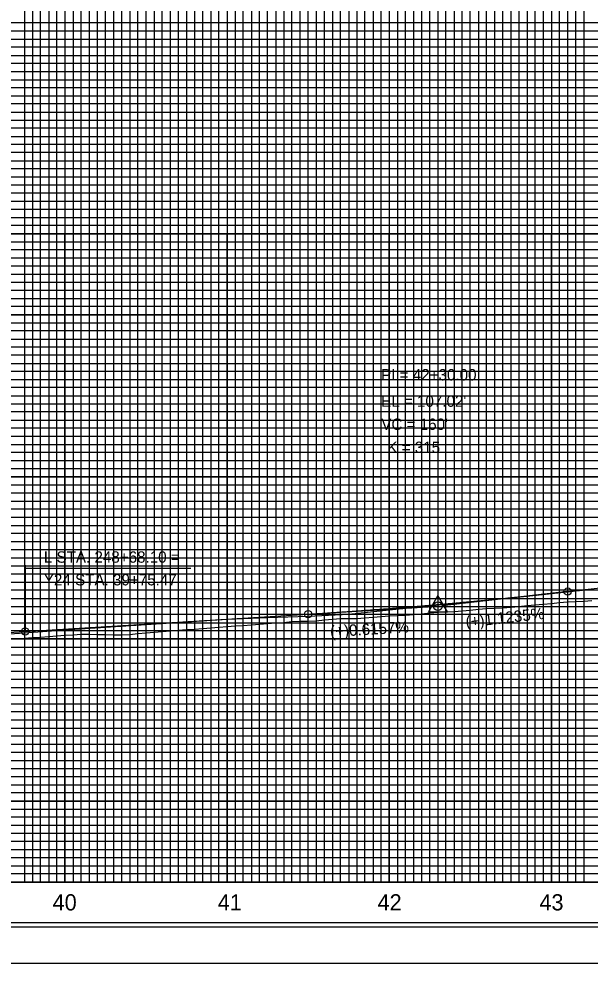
# Model space of a CAD drawing. Extents: x 2345490 to 2436403, y 465165 to 573888.
# Drawn here: x 2384738 to 2385091, y 515088 to 515670 of the extents above; entities that cross this region are included whole.
import ezdxf

# ---------------------------------------------------------------- set-up
doc = ezdxf.new("R2010")
doc.units = 0
for name, color, linetype in [('Old_Level_1', 7, 'Continuous'), ('Old_Level_18', 7, 'Continuous'), ('Old_Level_2', 7, 'Continuous'), ('Old_Level_3', 7, 'Continuous'), ('Old_Level_41', 7, 'Continuous'), ('Old_Level_42', 7, 'Continuous'), ('Old_Level_43', 7, 'Continuous'), ('Old_Level_50', 7, 'Continuous'), ('Old_Level_51', 7, 'Continuous'), ('Old_Level_57', 7, 'Continuous'), ('Old_Level_61', 7, 'Continuous'), ('Old_Level_62', 7, 'Continuous'), ('Old_Level_63', 7, 'Continuous')]:
    doc.layers.add(name, color=color, linetype=linetype)

msp = doc.modelspace()

# ---------------------------------------------------------------- linework, layer by layer
at = {"layer": 'Old_Level_1'}
for points in [[(2384766.799, 515289.75575), (2384771.799, 515290.10525), (2384776.799, 515290.37575), (2384781.799, 515290.40025), (2384786.799, 515290.303), (2384791.799, 515290.20375), (2384796.799, 515290.1025), (2384801.799, 515289.9995), (2384806.799, 515290.20875), (2384811.799, 515290.93725), (2384816.799, 515291.29), (2384821.799, 515291.61975), (2384826.799, 515292.0715), (2384831.799, 515292.55775), (2384836.799, 515292.92775), (2384841.799, 515293.286), (2384846.799, 515293.642), (2384851.799, 515294.027), (2384856.799, 515294.433), (2384861.799, 515294.83025), (2384866.799, 515295.1785), (2384871.799, 515295.52475), (2384876.799, 515295.869), (2384881.799, 515296.26675), (2384886.799, 515296.664), (2384891.799, 515297.05825), (2384896.799, 515297.394), (2384901.799, 515297.728), (2384906.799, 515298.30625), (2384911.799, 515298.3895), (2384916.799, 515298.471), (2384921.799, 515298.69675), (2384926.799, 515299.20875), (2384931.799, 515299.719), (2384936.799, 515300.07525), (2384941.799, 515300.148), (2384946.799, 515300.2205), (2384951.799, 515300.44075), (2384956.799, 515300.94775), (2384961.799, 515301.45475), (2384966.799, 515301.793), (2384971.799, 515302.0295), (2384976.799, 515302.266), (2384981.799, 515302.5435), (2384986.799, 515303.05425), (2384991.799, 515303.565), (2384996.799, 515304.03225), (2385001.799, 515304.2685), (2385006.799, 515304.50475), (2385011.799, 515304.782), (2385016.799, 515305.293), (2385021.799, 515305.804), (2385026.799, 515306.27125), (2385031.799, 515306.50725), (2385036.799, 515306.74325), (2385041.799, 515307.02025), (2385046.799, 515307.5315), (2385051.799, 515308.04275), (2385056.799, 515308.519), (2385061.799, 515308.86675), (2385066.799, 515309.378), (2385071.799, 515309.88925), (2385076.799, 515310.32875), (2385081.799, 515310.621), (2385086.799, 515310.91325), (2385091.799, 515311.27425)], [(2384736.799, 515287.50825), (2384741.799, 515287.97125), (2384746.799, 515288.333), (2384751.799, 515288.69225), (2384756.799, 515289.04925), (2384761.799, 515289.40375), (2384766.799, 515289.75575)]]:
    msp.add_lwpolyline(points, dxfattribs=at)
at = {"layer": 'Old_Level_18'}
msp.add_lwpolyline([(2386016.79875, 516162.5265), (2384516.79875, 516162.5265), (2384516.79875, 515112.5265), (2386016.79875, 515112.5265)], close=True, dxfattribs=at)
at = {"layer": 'Old_Level_2'}
for p, q in [((2384742.26875, 515292.0555), (2384742.26875, 515331.041)), ((2385076.799, 515316.71475), (2384999.532, 515308.034)), ((2385076.799, 515316.71475), (2385096.799, 515318.962)), ((2384626.799, 515284.94625), (2384916.799, 515302.80125)), ((2384916.799, 515302.80125), (2384994.05425, 515307.558))]:
    msp.add_line(p, q, dxfattribs=at)
msp.add_lwpolyline([(2384990.99325, 515304.27575), (2385002.73575, 515304.27575), (2384996.86475, 515314.4015)], close=True, dxfattribs=at)
for centre, radius in [((2385076.799, 515316.71475), 2.25), ((2384996.799, 515307.72675), 2.75), ((2384996.799, 515307.72675), 2.75), ((2384916.799, 515302.80125), 2.25), ((2384742.26875, 515292.0555), 2.25)]:
    msp.add_circle(centre, radius, dxfattribs=at)
msp.add_spline([(2384916.799, 515302.80125), (2384919.999, 515302.99975), (2384923.199, 515303.20175), (2384926.399, 515303.40675), (2384929.599, 515303.61525), (2384932.799, 515303.82675), (2384935.999, 515304.04175), (2384939.199, 515304.26), (2384942.399, 515304.48125), (2384945.599, 515304.706), (2384948.799, 515304.93375), (2384951.999, 515305.165), (2384955.199, 515305.3995), (2384958.399, 515305.637), (2384961.599, 515305.878), (2384964.799, 515306.122), (2384967.999, 515306.3695), (2384971.199, 515306.62), (2384974.399, 515306.874), (2384977.599, 515307.13125), (2384980.799, 515307.3915), (2384983.999, 515307.65525), (2384987.199, 515307.922), (2384990.399, 515308.19225), (2384993.599, 515308.46575), (2384996.799, 515308.74225), (2384999.999, 515309.02225), (2385003.199, 515309.30525), (2385006.399, 515309.59175), (2385009.599, 515309.8815), (2385012.799, 515310.17425), (2385015.999, 515310.4705), (2385019.199, 515310.76975), (2385022.399, 515311.0725), (2385025.599, 515311.3785), (2385028.799, 515311.6875), (2385031.999, 515312), (2385035.199, 515312.3155), (2385038.399, 515312.6345), (2385041.599, 515312.95675), (2385044.799, 515313.282), (2385047.999, 515313.61075), (2385051.199, 515313.94275), (2385054.399, 515314.27775), (2385057.599, 515314.61625), (2385060.799, 515314.95775), (2385063.999, 515315.30275), (2385067.199, 515315.651), (2385070.399, 515316.00225), (2385073.599, 515316.357), (2385076.799, 515316.71475)], degree=3, dxfattribs=at)
at = {"layer": 'Old_Level_3'}
for p, q in [((2384742.26875, 515332.9975), (2384742.26875, 515292.0555)), ((2384844.445, 515331.041), (2384742.26875, 515331.041))]:
    msp.add_line(p, q, dxfattribs=at)
at = {"layer": 'Old_Level_41'}
msp.add_line((2386016.79875, 515137.5265), (2384516.79875, 515137.5265), dxfattribs=at)
for points in [[(2384516.79875, 516162.5265), (2384566.79875, 516162.5265), (2384566.79875, 515137.5265), (2384616.79875, 515137.5265), (2384616.79875, 516162.5265), (2384666.79875, 516162.5265), (2384666.79875, 515137.5265), (2384716.79875, 515137.5265), (2384716.79875, 516162.5265), (2384766.79875, 516162.5265), (2384766.79875, 515137.5265), (2384816.79875, 515137.5265), (2384816.79875, 516162.5265), (2384866.79875, 516162.5265), (2384866.79875, 515137.5265), (2384916.79875, 515137.5265), (2384916.79875, 516162.5265), (2384966.79875, 516162.5265), (2384966.79875, 515137.5265), (2385016.79875, 515137.5265), (2385016.79875, 516162.5265), (2385066.79875, 516162.5265), (2385066.79875, 515137.5265), (2385116.79875, 515137.5265)], [(2384591.79875, 515137.5265), (2384591.79875, 516162.5265), (2384641.79875, 516162.5265), (2384641.79875, 515137.5265), (2384691.79875, 515137.5265), (2384691.79875, 516162.5265), (2384741.79875, 516162.5265), (2384741.79875, 515137.5265), (2384791.79875, 515137.5265), (2384791.79875, 516162.5265), (2384841.79875, 516162.5265), (2384841.79875, 515137.5265), (2384891.79875, 515137.5265), (2384891.79875, 516162.5265), (2384941.79875, 516162.5265), (2384941.79875, 515137.5265), (2384991.79875, 515137.5265), (2384991.79875, 516162.5265), (2385041.79875, 516162.5265), (2385041.79875, 515137.5265), (2385091.79875, 515137.5265)], [(2386016.79875, 515662.5265), (2384516.79875, 515662.5265), (2384516.79875, 515612.5265), (2386016.79875, 515612.5265)], [(2386016.79875, 515562.5265), (2384516.79875, 515562.5265), (2384516.79875, 515512.5265), (2386016.79875, 515512.5265)], [(2386016.79875, 515487.5265), (2384516.79875, 515487.5265), (2384516.79875, 515537.5265), (2386016.79875, 515537.5265)], [(2386016.79875, 515462.5265), (2384516.79875, 515462.5265), (2384516.79875, 515412.5265), (2386016.79875, 515412.5265)], [(2386016.79875, 515387.5265), (2384516.79875, 515387.5265), (2384516.79875, 515437.5265), (2386016.79875, 515437.5265)], [(2386016.79875, 515362.5265), (2384516.79875, 515362.5265), (2384516.79875, 515312.5265), (2386016.79875, 515312.5265)], [(2386016.79875, 515262.5265), (2384516.79875, 515262.5265), (2384516.79875, 515212.5265), (2386016.79875, 515212.5265)], [(2386016.79875, 515187.5265), (2384516.79875, 515187.5265), (2384516.79875, 515237.5265), (2386016.79875, 515237.5265)], [(2386016.79875, 515162.5265), (2384516.79875, 515162.5265)]]:
    msp.add_lwpolyline(points, dxfattribs=at)
at = {"layer": 'Old_Level_42'}
for points in [[(2386016.79875, 515587.5265), (2384516.79875, 515587.5265), (2384516.79875, 515637.5265), (2386016.79875, 515637.5265)], [(2386016.79875, 515287.5265), (2384516.79875, 515287.5265), (2384516.79875, 515337.5265), (2386016.79875, 515337.5265)]]:
    msp.add_lwpolyline(points, dxfattribs=at)
at = {"layer": 'Old_Level_43'}
for points in [[(2384746.79875, 516162.5265), (2384746.79875, 515137.5265), (2384751.79875, 515137.5265), (2384751.79875, 516162.5265)], [(2384756.79875, 516162.5265), (2384756.79875, 515137.5265), (2384761.79875, 515137.5265), (2384761.79875, 516162.5265)], [(2384771.79875, 516162.5265), (2384771.79875, 515137.5265), (2384776.79875, 515137.5265), (2384776.79875, 516162.5265)], [(2384781.79875, 516162.5265), (2384781.79875, 515137.5265), (2384786.79875, 515137.5265), (2384786.79875, 516162.5265)], [(2384796.79875, 516162.5265), (2384796.79875, 515137.5265), (2384801.79875, 515137.5265), (2384801.79875, 516162.5265)], [(2384806.79875, 516162.5265), (2384806.79875, 515137.5265), (2384811.79875, 515137.5265), (2384811.79875, 516162.5265)], [(2384821.79875, 516162.5265), (2384821.79875, 515137.5265), (2384826.79875, 515137.5265), (2384826.79875, 516162.5265)], [(2384831.79875, 516162.5265), (2384831.79875, 515137.5265), (2384836.79875, 515137.5265), (2384836.79875, 516162.5265)], [(2384846.79875, 516162.5265), (2384846.79875, 515137.5265), (2384851.79875, 515137.5265), (2384851.79875, 516162.5265)], [(2384856.79875, 516162.5265), (2384856.79875, 515137.5265), (2384861.79875, 515137.5265), (2384861.79875, 516162.5265)], [(2384871.79875, 516162.5265), (2384871.79875, 515137.5265), (2384876.79875, 515137.5265), (2384876.79875, 516162.5265)], [(2384881.79875, 516162.5265), (2384881.79875, 515137.5265), (2384886.79875, 515137.5265), (2384886.79875, 516162.5265)], [(2384896.79875, 516162.5265), (2384896.79875, 515137.5265), (2384911.79875, 515137.5265), (2384911.79875, 516162.5265)], [(2384901.79875, 516162.5265), (2384901.79875, 515137.5265), (2384906.79875, 515137.5265), (2384906.79875, 516162.5265)], [(2384901.79875, 516161.9265), (2384901.79875, 515137.5265), (2384906.79875, 515137.5265), (2384906.79875, 516161.9265)], [(2384921.79875, 516162.5265), (2384921.79875, 515137.5265), (2384926.79875, 515137.5265), (2384926.79875, 516162.5265)], [(2384931.79875, 516162.5265), (2384931.79875, 515137.5265), (2384936.79875, 515137.5265), (2384936.79875, 516162.5265)], [(2384946.79875, 516162.5265), (2384946.79875, 515137.5265), (2384951.79875, 515137.5265), (2384951.79875, 516162.5265)], [(2384956.79875, 516162.5265), (2384956.79875, 515137.5265), (2384961.79875, 515137.5265), (2384961.79875, 516162.5265)], [(2384971.79875, 516162.5265), (2384971.79875, 515137.5265), (2384976.79875, 515137.5265), (2384976.79875, 516162.5265)], [(2384981.79875, 516162.5265), (2384981.79875, 515137.5265), (2384986.79875, 515137.5265), (2384986.79875, 516162.5265)], [(2384996.79875, 516162.5265), (2384996.79875, 515137.5265), (2385001.79875, 515137.5265), (2385001.79875, 516162.5265)], [(2385006.79875, 516162.5265), (2385006.79875, 515137.5265), (2385011.79875, 515137.5265), (2385011.79875, 516162.5265)], [(2385021.79875, 516162.5265), (2385021.79875, 515137.5265), (2385026.79875, 515137.5265), (2385026.79875, 516162.5265)], [(2385031.79875, 516162.5265), (2385031.79875, 515137.5265), (2385036.79875, 515137.5265), (2385036.79875, 516162.5265)], [(2385046.79875, 516162.5265), (2385046.79875, 515137.5265)], [(2385051.79875, 516162.5265), (2385051.79875, 515137.5265), (2385056.79875, 515137.5265), (2385056.79875, 516162.5265), (2385061.79875, 516162.5265), (2385061.79875, 515137.5265), (2385071.79875, 515137.5265), (2385071.79875, 516162.5265), (2385076.79875, 516162.5265), (2385076.79875, 515137.5265), (2385081.79875, 515137.5265), (2385081.79875, 516162.5265), (2385086.79875, 516162.5265), (2385086.79875, 515137.5265)], [(2385966.79875, 515667.5265), (2384566.79875, 515667.5265), (2384566.79875, 515657.5265), (2385966.79875, 515657.5265)], [(2385966.79875, 515652.5265), (2384566.79875, 515652.5265), (2384566.79875, 515647.5265), (2385966.79875, 515647.5265)], [(2385966.79875, 515642.5265), (2384566.79875, 515642.5265)], [(2384566.79875, 515632.5265), (2385966.79875, 515632.5265)], [(2385966.79875, 515627.5265), (2384566.79875, 515627.5265), (2384566.79875, 515622.5265), (2385966.79875, 515622.5265)], [(2385966.79875, 515617.5265), (2384566.79875, 515617.5265), (2384566.79875, 515607.5265), (2385966.79875, 515607.5265)], [(2385966.79875, 515602.5265), (2384566.79875, 515602.5265), (2384566.79875, 515597.5265), (2385966.79875, 515597.5265)], [(2385966.79875, 515592.5265), (2384566.79875, 515592.5265), (2384566.79875, 515582.5265), (2385966.79875, 515582.5265)], [(2385966.79875, 515577.5265), (2384566.79875, 515577.5265), (2384566.79875, 515572.5265), (2385966.79875, 515572.5265)], [(2385966.79875, 515567.5265), (2384566.79875, 515567.5265), (2384566.79875, 515557.5265), (2385966.79875, 515557.5265)], [(2385966.79875, 515552.5265), (2384566.79875, 515552.5265), (2384566.79875, 515547.5265), (2385966.79875, 515547.5265)], [(2385966.79875, 515542.5265), (2384566.79875, 515542.5265), (2384566.79875, 515532.5265), (2385966.79875, 515532.5265)], [(2385966.79875, 515527.5265), (2384566.79875, 515527.5265), (2384566.79875, 515522.5265), (2385966.79875, 515522.5265)], [(2385966.79875, 515517.5265), (2384566.79875, 515517.5265), (2384566.79875, 515507.5265), (2385966.79875, 515507.5265)], [(2385966.79875, 515502.5265), (2384566.79875, 515502.5265), (2384566.79875, 515497.5265), (2385966.79875, 515497.5265)], [(2385966.79875, 515492.5265), (2384566.79875, 515492.5265), (2384566.79875, 515482.5265), (2385966.79875, 515482.5265)], [(2385966.79875, 515477.5265), (2384566.79875, 515477.5265), (2384566.79875, 515472.5265), (2385966.79875, 515472.5265)], [(2385966.79875, 515467.5265), (2384566.79875, 515467.5265), (2384566.79875, 515457.5265), (2385966.79875, 515457.5265)], [(2385966.79875, 515452.5265), (2384566.79875, 515452.5265), (2384566.79875, 515447.5265), (2385966.79875, 515447.5265)], [(2385966.79875, 515442.5265), (2384566.79875, 515442.5265), (2384566.79875, 515432.5265), (2385966.79875, 515432.5265)], [(2385966.79875, 515427.5265), (2384566.79875, 515427.5265), (2384566.79875, 515422.5265), (2385966.79875, 515422.5265)], [(2385966.79875, 515417.5265), (2384566.79875, 515417.5265), (2384566.79875, 515407.5265), (2385966.79875, 515407.5265)], [(2385966.79875, 515402.5265), (2384566.79875, 515402.5265), (2384566.79875, 515397.5265), (2385966.79875, 515397.5265)], [(2385966.79875, 515392.5265), (2384566.79875, 515392.5265), (2384566.79875, 515382.5265), (2385966.79875, 515382.5265)], [(2385966.79875, 515377.5265), (2384566.79875, 515377.5265), (2384566.79875, 515372.5265), (2385966.79875, 515372.5265)], [(2385966.79875, 515367.5265), (2384566.79875, 515367.5265), (2384566.79875, 515357.5265), (2385966.79875, 515357.5265)], [(2385966.79875, 515352.5265), (2384566.79875, 515352.5265), (2384566.79875, 515347.5265), (2385966.79875, 515347.5265)], [(2385966.79875, 515342.5265), (2384566.79875, 515342.5265)], [(2384566.79875, 515332.5265), (2385966.79875, 515332.5265)], [(2385966.79875, 515327.5265), (2384566.79875, 515327.5265), (2384566.79875, 515322.5265), (2385966.79875, 515322.5265)], [(2385966.79875, 515317.5265), (2384566.79875, 515317.5265)], [(2384566.79875, 515307.5265), (2385966.79875, 515307.5265)], [(2385966.79875, 515302.5265), (2384566.79875, 515302.5265), (2384566.79875, 515297.5265), (2385966.79875, 515297.5265)], [(2385966.79875, 515292.5265), (2384566.79875, 515292.5265), (2384566.79875, 515282.5265), (2385966.79875, 515282.5265)], [(2385966.79875, 515277.5265), (2384566.79875, 515277.5265), (2384566.79875, 515272.5265), (2385966.79875, 515272.5265)], [(2385966.79875, 515267.5265), (2384566.79875, 515267.5265), (2384566.79875, 515257.5265), (2385966.79875, 515257.5265)], [(2385966.79875, 515252.5265), (2384566.79875, 515252.5265), (2384566.79875, 515247.5265), (2385966.79875, 515247.5265)], [(2385966.79875, 515242.5265), (2384566.79875, 515242.5265), (2384566.79875, 515232.5265), (2385966.79875, 515232.5265)], [(2385966.79875, 515227.5265), (2384566.79875, 515227.5265), (2384566.79875, 515222.5265), (2385966.79875, 515222.5265)], [(2385966.79875, 515217.5265), (2384566.79875, 515217.5265), (2384566.79875, 515207.5265), (2385966.79875, 515207.5265)], [(2385966.79875, 515202.5265), (2384566.79875, 515202.5265), (2384566.79875, 515197.5265), (2385966.79875, 515197.5265)], [(2385966.79875, 515192.5265), (2384566.79875, 515192.5265), (2384566.79875, 515182.5265), (2385966.79875, 515182.5265)], [(2385966.79875, 515177.5265), (2384566.79875, 515177.5265), (2384566.79875, 515172.5265), (2385966.79875, 515172.5265)], [(2385966.79875, 515167.5265), (2384566.79875, 515167.5265), (2384566.79875, 515157.5265), (2385966.79875, 515157.5265)], [(2385966.79875, 515152.5265), (2384566.79875, 515152.5265), (2384566.79875, 515147.5265), (2385966.79875, 515147.5265)], [(2385966.79875, 515142.5265), (2384566.79875, 515142.5265)]]:
    msp.add_lwpolyline(points, dxfattribs=at)
at = {"layer": 'Old_Level_50'}
msp.add_lwpolyline([(2386029.29875, 516165.0765), (2384362.79875, 516165.0765), (2384362.79875, 515109.9765), (2386029.29875, 515109.9765)], close=True, dxfattribs=at)
at = {"layer": 'Old_Level_51'}
msp.add_lwpolyline([(2386033.79875, 516187.5265), (2384349.79875, 516187.5265), (2384349.79875, 515087.5265), (2386033.79875, 515087.5265)], close=True, dxfattribs=at)
at = {"layer": 'Old_Level_57'}
for p, q in [((2381716.79925, 515537.52675), (2386366.79875, 515537.52675)), ((2384766.79875, 515137.52675), (2384766.79875, 515537.52675)), ((2384766.79875, 515137.62675), (2384766.79875, 515537.52675)), ((2384866.79875, 515137.52675), (2384866.79875, 515537.52675)), ((2384866.79875, 515137.62675), (2384866.79875, 515537.52675)), ((2384966.79875, 515137.52675), (2384966.79875, 515537.52675)), ((2384966.79875, 515137.62675), (2384966.79875, 515537.52675)), ((2384966.79875, 515137.62675), (2384966.79875, 515537.52675)), ((2385066.79875, 515137.52675), (2385066.79875, 515537.52675)), ((2385066.79875, 515137.62675), (2385066.79875, 515537.52675)), ((2381716.79925, 515487.52675), (2386366.79875, 515487.52675)), ((2381716.79925, 515437.52675), (2386366.79875, 515437.52675)), ((2381716.79925, 515387.52675), (2386366.79875, 515387.52675)), ((2381716.79925, 515337.52675), (2386366.79875, 515337.52675)), ((2381716.79925, 515287.52675), (2386366.79875, 515287.52675)), ((2381716.79925, 515237.52675), (2386366.79875, 515237.52675)), ((2381716.799, 515187.52675), (2386366.79875, 515187.52675)), ((2381716.79925, 515137.52675), (2386366.79875, 515137.52675))]:
    msp.add_line(p, q, dxfattribs=at)
at = {"layer": 'Old_Level_61'}
msp.add_lwpolyline([(2384716.799, 515289.63325), (2384741.799, 515291.33275), (2384766.799, 515293.0715), (2384791.799, 515294.74525), (2384816.799, 515296.35375), (2384841.799, 515297.97775), (2384866.799, 515299.72725), (2384891.799, 515300.81875), (2384916.799, 515301.54), (2384941.799, 515302.888), (2384966.799, 515305.4225), (2384991.799, 515307.97475), (2385016.799, 515310.507), (2385041.799, 515312.8505), (2385066.799, 515315.50575), (2385091.799, 515318.182)], dxfattribs=at)
at = {"layer": 'Old_Level_63'}
msp.add_line((2381766.79875, 515137.5265), (2386228.05125, 515137.5265), dxfattribs=at)

# ---------------------------------------------------------------- texts
at = {"layer": 'Old_Level_2'}
for s, height, p in [('PI = 42+30.00', 7.0000005, (2384961.799, 515446.9895)), ("EL = 107.02'", 7.0000005, (2384961.799, 515430.72675)), ("VC = 160'", 7.000001, (2384961.927, 515416.48125)), ('K = 315', 7.000001, (2384965.66325, 515402.24275))]:
    msp.add_text(s, height=height, dxfattribs=at).set_placement(p)
for s, rotation, p in [('(+)1.1235%', 6.41046667, (2385014.273, 515294.4955)), ('(+)0.6157%', 3.523175, (2384930.5385, 515288.61525))]:
    msp.add_text(s, height=7.000001, rotation=rotation, dxfattribs=at).set_placement(p)
at = {"layer": 'Old_Level_3'}
for s, p in [('L STA. 248+68.10 = ', (2384753.8015, 515334.54025)), ('Y24 STA. 39+75.47', (2384753.8015, 515320.54025))]:
    msp.add_text(s, height=7.0000005, dxfattribs=at).set_placement(p)
at = {"layer": 'Old_Level_62'}
for s, p in [('40', (2384759.1855, 515120.0265)), ('41', (2384861.025, 515120.0265)), ('42', (2384959.57325, 515120.0265)), ('43', (2385059.408, 515120.0265))]:
    msp.add_text(s, height=10.000001, dxfattribs=at).set_placement(p)

doc.saveas('drawing.dxf')
